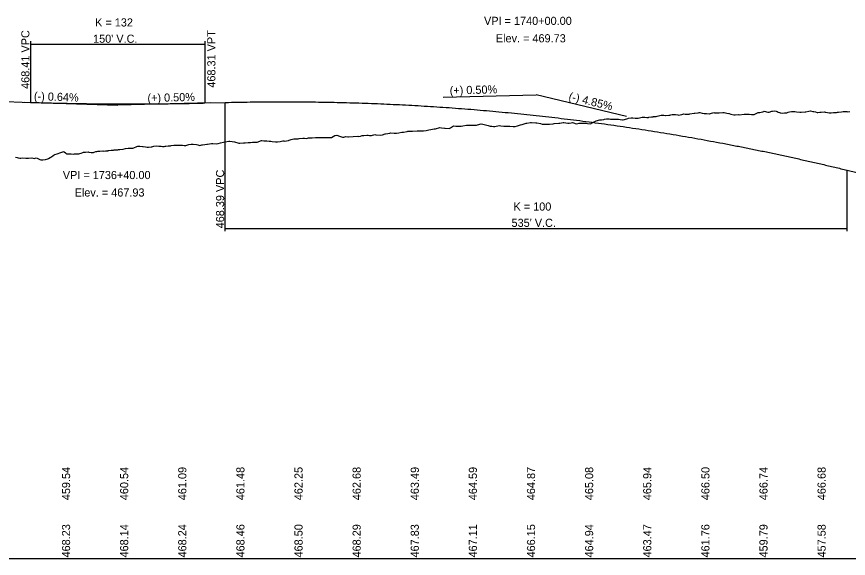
# Model space of a CAD drawing. Extents: x 2017200 to 2047700, y 854850 to 893350.
# Drawn here: x 2021053 to 2021769, y 871100 to 871566 of the extents above; entities that cross this region are included whole.
import ezdxf

# ---------------------------------------------------------------- set-up
doc = ezdxf.new("R2010")
doc.units = 0
for name, color, linetype in [('RD_DDB_GradeTX', 7, 'Continuous'), ('RD_DDB_Profile_EX', 7, 'Continuous'), ('RD_DDB_Profile_Lbl', 7, 'Continuous'), ('RD_DDB_Profile_PR', 7, 'Continuous'), ('RD_DDB_StripGrade', 7, 'Continuous'), ('RD_DDB_VCLbl', 7, 'Continuous'), ('RD_GPK_Profile_Cell', 7, 'Continuous')]:
    doc.layers.add(name, color=color, linetype=linetype)

msp = doc.modelspace()

# ---------------------------------------------------------------- linework, layer by layer
at = {"layer": 'RD_DDB_GradeTX'}
for p, q in [((2021420.02, 871496.65), (2021500, 871498.65)), ((2021577.74, 871479.78), (2021500, 871498.65)), ((2021060.04, 871492.2), (2021140, 871489.65)), ((2021219.98, 871491.65), (2021140, 871489.65))]:
    msp.add_line(p, q, dxfattribs=at)
at = {"layer": 'RD_DDB_Profile_EX'}
msp.add_lwpolyline([(2021051.98, 871444.9), (2021053.44, 871444.57), (2021054.24, 871444.39), (2021055.89, 871444.21), (2021056.7, 871444.11), (2021058.34, 871444.22), (2021060.79, 871444.1), (2021061.39, 871444.07), (2021062.05, 871444.15), (2021063.24, 871444.2), (2021066.04, 871444.33), (2021068.14, 871443.88), (2021069.92, 871444.26), (2021070.66, 871444.12), (2021073.05, 871443.06), (2021073.88, 871442.7), (2021075.5, 871442.78), (2021077.95, 871442.93), (2021079.8, 871443.58), (2021080.4, 871443.86), (2021081.87, 871444.54), (2021082.85, 871445.26), (2021084.32, 871446.34), (2021085.3, 871446.94), (2021085.88, 871447.29), (2021087.75, 871447.88), (2021088.81, 871448.21), (2021090.21, 871448.72), (2021092.66, 871449.57), (2021093.27, 871449.78), (2021093.98, 871449.62), (2021095.11, 871448.56), (2021095.77, 871447.94), (2021098.06, 871447.73), (2021100.01, 871447.69), (2021102.16, 871447.65), (2021102.76, 871447.67), (2021104.91, 871447.75), (2021106.49, 871447.84), (2021107.37, 871448.1), (2021108.5, 871448.43), (2021109.82, 871448.92), (2021110.42, 871449.14), (2021110.85, 871449.27), (2021112.27, 871449.33), (2021114.72, 871449.39), (2021115.17, 871449.26), (2021117.17, 871449.09), (2021118.76, 871448.96), (2021119.11, 871448.99), (2021119.62, 871449.13), (2021121.24, 871449.68), (2021122.07, 871449.84), (2021122.97, 871450.02), (2021123.75, 871450.2), (2021124.53, 871450.21), (2021127.2, 871450.24), (2021128, 871450.23), (2021129.43, 871450.35), (2021131.45, 871450.51), (2021131.88, 871450.56), (2021132.23, 871450.6), (2021134.33, 871450.84), (2021135.73, 871451.01), (2021136.44, 871451.07), (2021136.78, 871451.1), (2021139.23, 871451.31), (2021140.03, 871451.37), (2021140.62, 871451.43), (2021141.68, 871451.54), (2021144.78, 871451.87), (2021146.7, 871452.28), (2021149.04, 871452.73), (2021151.49, 871452.71), (2021152.2, 871452.71), (2021153.1, 871452.72), (2021153.94, 871453.06), (2021156.39, 871454.04), (2021157.14, 871454.34), (2021157.51, 871454.45), (2021158.84, 871454.37), (2021161.3, 871454.21), (2021161.94, 871454), (2021163.75, 871453.7), (2021165.27, 871453.44), (2021166.41, 871453.42), (2021168.65, 871453.8), (2021169.31, 871453.91), (2021171.1, 871454.26), (2021173.55, 871454.59), (2021175.42, 871454.52), (2021176, 871454.5), (2021176.43, 871454.49), (2021177.32, 871454.4), (2021178.56, 871454.13), (2021179.98, 871454.15), (2021180.91, 871454.27), (2021181.3, 871454.32), (2021183.36, 871454.63), (2021184.57, 871454.81), (2021185.27, 871454.75), (2021185.81, 871454.84), (2021188.26, 871455.2), (2021189.37, 871455.35), (2021190.71, 871455.36), (2021193.14, 871455.37), (2021193.83, 871455.21), (2021195.59, 871455.22), (2021197.07, 871454.83), (2021198.48, 871455.08), (2021201, 871455.72), (2021203.12, 871456.09), (2021204.93, 871456.23), (2021207.77, 871455.8), (2021208.86, 871455.57), (2021210.49, 871455.01), (2021212.42, 871455.48), (2021212.79, 871455.5), (2021214.86, 871455.79), (2021216.72, 871456.04), (2021217.06, 871456.05), (2021220.65, 871456.76), (2021221.71, 871456.75), (2021224.58, 871456.29), (2021226.36, 871456.71), (2021228.51, 871457.2), (2021231, 871457.76), (2021232.44, 871458.02), (2021235.65, 871458.6), (2021236.37, 871458.63), (2021240.32, 871457.99), (2021244.23, 871457.03), (2021244.94, 871457.04), (2021248.16, 871457.27), (2021249.59, 871457.39), (2021252.09, 871457.44), (2021254.24, 871457.57), (2021256.02, 871457.75), (2021258.88, 871457.82), (2021259.95, 871457.87), (2021263.53, 871459.13), (2021263.88, 871459.22), (2021265.79, 871459.08), (2021267.81, 871458.91), (2021268.18, 871458.9), (2021270.11, 871458.83), (2021271.74, 871458.66), (2021272.82, 871458.39), (2021275.67, 871458.13), (2021277.47, 871458.21), (2021279.6, 871458.51), (2021282.12, 871458.94), (2021282.88, 871458.97), (2021283.53, 871458.81), (2021286.76, 871459.18), (2021287.46, 871459.48), (2021289.27, 871460.11), (2021291.41, 871460.65), (2021295.31, 871460.8), (2021296.06, 871460.86), (2021299.24, 871461.21), (2021300.7, 871461.26), (2021302.04, 871461.08), (2021303.17, 871461.4), (2021304.17, 871461.58), (2021305.35, 871461.63), (2021307.1, 871461.52), (2021310, 871461.73), (2021311.03, 871461.82), (2021314.64, 871461.81), (2021314.96, 871461.81), (2021316.72, 871461.78), (2021318.89, 871461.72), (2021319.29, 871461.73), (2021321.2, 871461.84), (2021322.82, 871461.82), (2021323.94, 871461.96), (2021326.75, 871463.65), (2021328.58, 871463.93), (2021330.68, 871462.87), (2021333.23, 871462.11), (2021333.98, 871462.09), (2021334.61, 871462.15), (2021336.11, 871462.62), (2021337.88, 871462.56), (2021338.54, 871462.47), (2021342.52, 871462.61), (2021346.4, 871462.85), (2021347.17, 871462.81), (2021348.88, 871463.11), (2021350.33, 871463.46), (2021351.82, 871463.62), (2021354.26, 871463.85), (2021355.27, 871463.71), (2021356.46, 871463.63), (2021358.19, 871463.5), (2021361.11, 871464.29), (2021362.12, 871464.25), (2021366.05, 871463.74), (2021367.65, 871464.19), (2021369.98, 871464.9), (2021370.4, 871464.93), (2021372.3, 871465.4), (2021373.91, 871465.56), (2021375.05, 871465.77), (2021377.84, 871465.68), (2021379.7, 871465.5), (2021381.77, 871465.97), (2021384.34, 871466.29), (2021385.08, 871466.38), (2021385.7, 871466.35), (2021388.99, 871467.1), (2021389.63, 871467.16), (2021393.11, 871467.28), (2021393.64, 871467.3), (2021397.49, 871467.47), (2021398.28, 871467.49), (2021401.42, 871467.45), (2021402.93, 871467.58), (2021405.35, 871467.85), (2021407.58, 871468.47), (2021409.28, 871468.79), (2021412.22, 871469.24), (2021413.2, 871469.37), (2021417.13, 871470.49), (2021418.58, 871470.22), (2021421.06, 871469.84), (2021421.52, 871469.78), (2021424.99, 871469.6), (2021426.16, 871470.28), (2021428.92, 871471.8), (2021430.81, 871471.72), (2021431.92, 871471.71), (2021432.85, 871471.69), (2021434.05, 871471.65), (2021435.46, 871471.52), (2021436.78, 871471.79), (2021440.1, 871472.59), (2021440.71, 871472.58), (2021444.04, 871472.48), (2021444.75, 871472.43), (2021448.57, 871472.56), (2021449.4, 871472.79), (2021452.5, 871473.62), (2021454.04, 871473.34), (2021456.43, 871472.65), (2021458.69, 871472.15), (2021460.36, 871471.66), (2021461.73, 871471.46), (2021463.34, 871471.22), (2021464.29, 871471.21), (2021468.22, 871472.13), (2021469.51, 871471.97), (2021472.15, 871471.64), (2021472.63, 871471.61), (2021476.08, 871471.66), (2021477.28, 871471.6), (2021480.01, 871471.21), (2021481.93, 871471.17), (2021483.94, 871471.74), (2021486.57, 871472.62), (2021487.87, 871472.97), (2021491.22, 871474.12), (2021491.8, 871474.2), (2021494.98, 871474.69), (2021495.87, 871474.77), (2021499.66, 871474.4), (2021500.51, 871474.33), (2021503.59, 871473.8), (2021505.16, 871473.41), (2021507.52, 871473.21), (2021509.81, 871473.36), (2021511.45, 871473.34), (2021514.45, 871473.66), (2021515.38, 871473.76), (2021519.31, 871474.08), (2021520.44, 871474.24), (2021523.24, 871474.68), (2021523.75, 871474.64), (2021527.17, 871474.14), (2021527.73, 871474.04), (2021528.39, 871474.12), (2021530, 871474.57), (2021531.1, 871474.88), (2021533.03, 871474.07), (2021533.53, 871473.96), (2021535.03, 871473.65), (2021537.05, 871474.07), (2021537.66, 871474.2), (2021538.98, 871474.08), (2021540.58, 871474.15), (2021542.27, 871474.23), (2021542.93, 871474.17), (2021544.1, 871474), (2021547.02, 871473.68), (2021547.63, 871474.07), (2021551.45, 871476.2), (2021554.84, 871476.94), (2021556.02, 871476.91), (2021558.21, 871477.44), (2021558.83, 871477.59), (2021560.57, 871477.9), (2021561.77, 871477.89), (2021562.83, 871477.83), (2021563.89, 871477.58), (2021565.26, 871477.47), (2021566.83, 871477.51), (2021568.78, 871477.55), (2021569.62, 871477.57), (2021570.85, 871477.62), (2021572.31, 871477.34), (2021574.13, 871476.99), (2021574.87, 871476.97), (2021575.84, 871477.31), (2021578.91, 871478.28), (2021579.36, 871478.35), (2021581.6, 871478.67), (2021583.09, 871478.83), (2021585.14, 871478.48), (2021586.41, 871478.42), (2021587, 871478.39), (2021587.56, 871478.48), (2021589.94, 871478.99), (2021591.07, 871479.24), (2021592, 871479.31), (2021593.46, 871479.2), (2021595.14, 871479.07), (2021596.44, 871479.11), (2021596.99, 871479.22), (2021599.22, 871479.67), (2021600.52, 871479.74), (2021600.86, 871479.76), (2021603.31, 871480.01), (2021604.04, 871480.13), (2021605.27, 871480.35), (2021607.57, 871480.99), (2021609.66, 871481.09), (2021611.09, 871480.89), (2021611.53, 871480.83), (2021614.04, 871481.03), (2021614.87, 871481.13), (2021615.65, 871481.36), (2021616.99, 871481.49), (2021618.41, 871481.67), (2021619.78, 871481.5), (2021621.67, 871481.3), (2021622.77, 871481.18), (2021623.93, 871481.34), (2021625.2, 871481.65), (2021627.11, 871482.12), (2021628.08, 871482.03), (2021628.72, 871482.02), (2021631.44, 871482), (2021632.25, 871482.15), (2021635.77, 871482.65), (2021636.09, 871482.68), (2021636.42, 871482.8), (2021639.3, 871483.17), (2021640.06, 871483.26), (2021640.6, 871483.33), (2021642.82, 871482.81), (2021644.35, 871482.46), (2021644.8, 871482.43), (2021646.35, 871482.37), (2021648.64, 871482.27), (2021649.01, 871482.27), (2021649.88, 871482.49), (2021652.91, 871483.27), (2021653.4, 871483.18), (2021657.46, 871483.02), (2021660.45, 871483.34), (2021661.7, 871483.45), (2021663.98, 871482.88), (2021665.64, 871482.47), (2021665.95, 871482.43), (2021667.5, 871482.04), (2021669.86, 871481.46), (2021670.22, 871481.43), (2021671.03, 871481.44), (2021674.08, 871481.48), (2021674.56, 871481.46), (2021678.78, 871482.03), (2021681.61, 871482), (2021682.47, 871481.99), (2021683.09, 871481.95), (2021685.13, 871481.68), (2021686.64, 871481.48), (2021687.4, 871481.59), (2021688.66, 871482.23), (2021690.81, 871483.32), (2021691.26, 871483.33), (2021691.72, 871483.19), (2021692.18, 871483.28), (2021694.97, 871483.81), (2021695.71, 871484.2), (2021696.06, 871484.38), (2021699.24, 871483.7), (2021700.41, 871483.69), (2021702.76, 871484.43), (2021703.25, 871484.59), (2021704.78, 871484.73), (2021706.29, 871484.36), (2021707.38, 871484.09), (2021708.24, 871483.73), (2021709.15, 871483.27), (2021709.81, 871483.13), (2021710.36, 871483.01), (2021711.49, 871482.82), (2021713.54, 871483), (2021715.6, 871483.09), (2021716.86, 871483.51), (2021717.95, 871483.87), (2021719.69, 871484.24), (2021720.39, 871484.2), (2021722.36, 871484.08), (2021723.92, 871483.97), (2021726.79, 871483.7), (2021727.44, 871483.69), (2021727.85, 871483.69), (2021731.24, 871483.92), (2021731.92, 871483.97), (2021734.49, 871484.43), (2021735.98, 871484.63), (2021738.02, 871484.23), (2021738.67, 871484.1), (2021740.17, 871483.79), (2021741.54, 871483.48), (2021742.22, 871483.33), (2021744.06, 871483.61), (2021744.65, 871483.63), (2021745.07, 871483.65), (2021748.09, 871483.8), (2021748.59, 871483.69), (2021749.15, 871483.56), (2021752.12, 871483.03), (2021753.67, 871483.12), (2021755.65, 871483.23), (2021756.12, 871483.26), (2021757.09, 871483.34), (2021758.2, 871483.45), (2021759.22, 871483.63), (2021760.12, 871483.55), (2021762.74, 871483.98), (2021764.11, 871484.27), (2021766.22, 871484.18), (2021767.31, 871484.13), (2021768.09, 871483.97), (2021769.75, 871484.33)], dxfattribs=at)
at = {"layer": 'RD_DDB_Profile_PR'}
for p, q in [((2020875, 871498.11), (2021065, 871492.04)), ((2021215, 871491.53), (2021232.5, 871491.96)), ((2021767.5, 871433.73), (2021822.5, 871420.38))]:
    msp.add_line(p, q, dxfattribs=at)
for points in [[(2021065, 871492.04), (2021068, 871491.95), (2021071, 871491.86), (2021074, 871491.77), (2021077, 871491.69), (2021080, 871491.61), (2021083, 871491.53), (2021086, 871491.46), (2021089, 871491.39), (2021092, 871491.32), (2021095, 871491.26), (2021098, 871491.2), (2021101, 871491.14), (2021104, 871491.09), (2021107, 871491.04), (2021110, 871490.99), (2021113, 871490.95), (2021116, 871490.91), (2021119, 871490.87), (2021122, 871490.84), (2021125, 871490.81), (2021128, 871490.79), (2021131, 871490.76), (2021134, 871490.74), (2021137, 871490.73), (2021140, 871490.72), (2021143, 871490.71), (2021146, 871490.7), (2021149, 871490.7), (2021152, 871490.7), (2021155, 871490.71), (2021158, 871490.72), (2021161, 871490.73), (2021164, 871490.74), (2021167, 871490.76), (2021170, 871490.78), (2021173, 871490.81), (2021176, 871490.84), (2021179, 871490.87), (2021182, 871490.91), (2021185, 871490.95), (2021188, 871490.99), (2021191, 871491.03), (2021194, 871491.08), (2021197, 871491.14), (2021200, 871491.19), (2021203, 871491.25), (2021206, 871491.32), (2021209, 871491.38), (2021212, 871491.45), (2021215, 871491.53)], [(2021232.5, 871491.96), (2021243.2, 871492.2), (2021253.9, 871492.38), (2021264.6, 871492.51), (2021275.3, 871492.57), (2021286, 871492.58), (2021296.7, 871492.54), (2021307.4, 871492.43), (2021318.1, 871492.27), (2021328.8, 871492.05), (2021339.5, 871491.77), (2021350.2, 871491.44), (2021360.9, 871491.05), (2021371.6, 871490.6), (2021382.3, 871490.09), (2021393, 871489.53), (2021403.7, 871488.91), (2021414.4, 871488.23), (2021425.1, 871487.5), (2021435.8, 871486.71), (2021446.5, 871485.86), (2021457.2, 871484.95), (2021467.9, 871483.98), (2021478.6, 871482.96), (2021489.3, 871481.88), (2021500, 871480.75), (2021510.7, 871479.56), (2021521.4, 871478.3), (2021532.1, 871477), (2021542.8, 871475.63), (2021553.5, 871474.21), (2021564.2, 871472.73), (2021574.9, 871471.19), (2021585.6, 871469.6), (2021596.3, 871467.95), (2021607, 871466.24), (2021617.7, 871464.47), (2021628.4, 871462.65), (2021639.1, 871460.77), (2021649.8, 871458.83), (2021660.5, 871456.84), (2021671.2, 871454.78), (2021681.9, 871452.67), (2021692.6, 871450.51), (2021703.3, 871448.28), (2021714, 871446), (2021724.7, 871443.66), (2021735.4, 871441.26), (2021746.1, 871438.81), (2021756.8, 871436.3), (2021767.5, 871433.73)]]:
    msp.add_spline(points, degree=3, dxfattribs=at)
at = {"layer": 'RD_DDB_VCLbl'}
for p, q in [((2021065, 871544.54), (2021065, 871492.04)), ((2021215, 871544.54), (2021215, 871491.53)), ((2021065, 871542.04), (2021215, 871542.04)), ((2021200, 871542.04), (2021215, 871542.04)), ((2021232.5, 871381.23), (2021232.5, 871491.96)), ((2021767.5, 871381.23), (2021767.5, 871433.73)), ((2021232.5, 871383.73), (2021767.5, 871383.73))]:
    msp.add_line(p, q, dxfattribs=at)
at = {"layer": 'RD_GPK_Profile_Cell'}
msp.add_line((2020500, 871100), (2022500, 871100), dxfattribs=at)

# ---------------------------------------------------------------- texts
at = {"layer": 'RD_DDB_GradeTX'}
for s, rotation, p in [('(+) 0.50%', 1.4321, (2021425.65, 871498.79)), ('(-) 0.64%', 358.17221, (2021067.78, 871493.96)), ('(+) 0.50%', 1.4321, (2021165.61, 871492.29)), ('(-) 4.85%', 346.35902, (2021527.37, 871494.07))]:
    msp.add_text(s, height=7, rotation=rotation, dxfattribs=at).set_placement(p)
at = {"layer": 'RD_DDB_Profile_Lbl'}
for s, p in [('VPI = 1740+00.00', (2021455.1, 871558.65)), ('Elev. = 469.73', (2021465.27, 871543.65)), ('VPI = 1736+40.00', (2021092.73, 871426.08)), ('Elev. = 467.93', (2021102.9, 871411.08))]:
    msp.add_text(s, height=7, dxfattribs=at).set_placement(p)
at = {"layer": 'RD_DDB_StripGrade'}
for s, p in [('468.41 VPC', (2021064, 871503.64)), ('468.31 VPT', (2021223.99, 871504.69)), ('468.39 VPC', (2021231.5, 871383.73)), ('459.54', (2021099, 871150)), ('460.54', (2021149, 871150)), ('461.09', (2021199, 871150)), ('461.48', (2021249, 871150)), ('462.25', (2021299, 871150)), ('462.68', (2021349, 871150)), ('463.49', (2021399, 871150)), ('464.59', (2021449, 871150)), ('464.87', (2021499, 871150)), ('465.08', (2021549, 871150)), ('465.94', (2021599, 871150)), ('466.50', (2021649, 871150)), ('466.74', (2021699, 871150)), ('466.68', (2021749, 871150)), ('468.23', (2021099, 871100.75)), ('468.14', (2021149, 871100.75)), ('468.24', (2021199, 871100.75)), ('468.46', (2021249, 871100.75)), ('468.50', (2021299, 871100.75)), ('468.29', (2021349, 871100.75)), ('467.83', (2021399, 871100.75)), ('467.11', (2021449, 871100.75)), ('466.15', (2021499, 871100.75)), ('464.94', (2021549, 871100.75)), ('463.47', (2021599, 871100.75)), ('461.76', (2021649, 871100.75)), ('459.79', (2021699, 871100.75)), ('457.58', (2021749, 871100.75))]:
    msp.add_text(s, height=7, rotation=90, dxfattribs=at).set_placement(p)
at = {"layer": 'RD_DDB_VCLbl'}
for s, p in [('K = 132', (2021120.52, 871557.29)), ("150' V.C.", (2021118.75, 871543.29)), ('K = 100', (2021480.44, 871398.98)), ("535' V.C.", (2021478.75, 871384.98))]:
    msp.add_text(s, height=7, dxfattribs=at).set_placement(p)

doc.saveas('drawing.dxf')
